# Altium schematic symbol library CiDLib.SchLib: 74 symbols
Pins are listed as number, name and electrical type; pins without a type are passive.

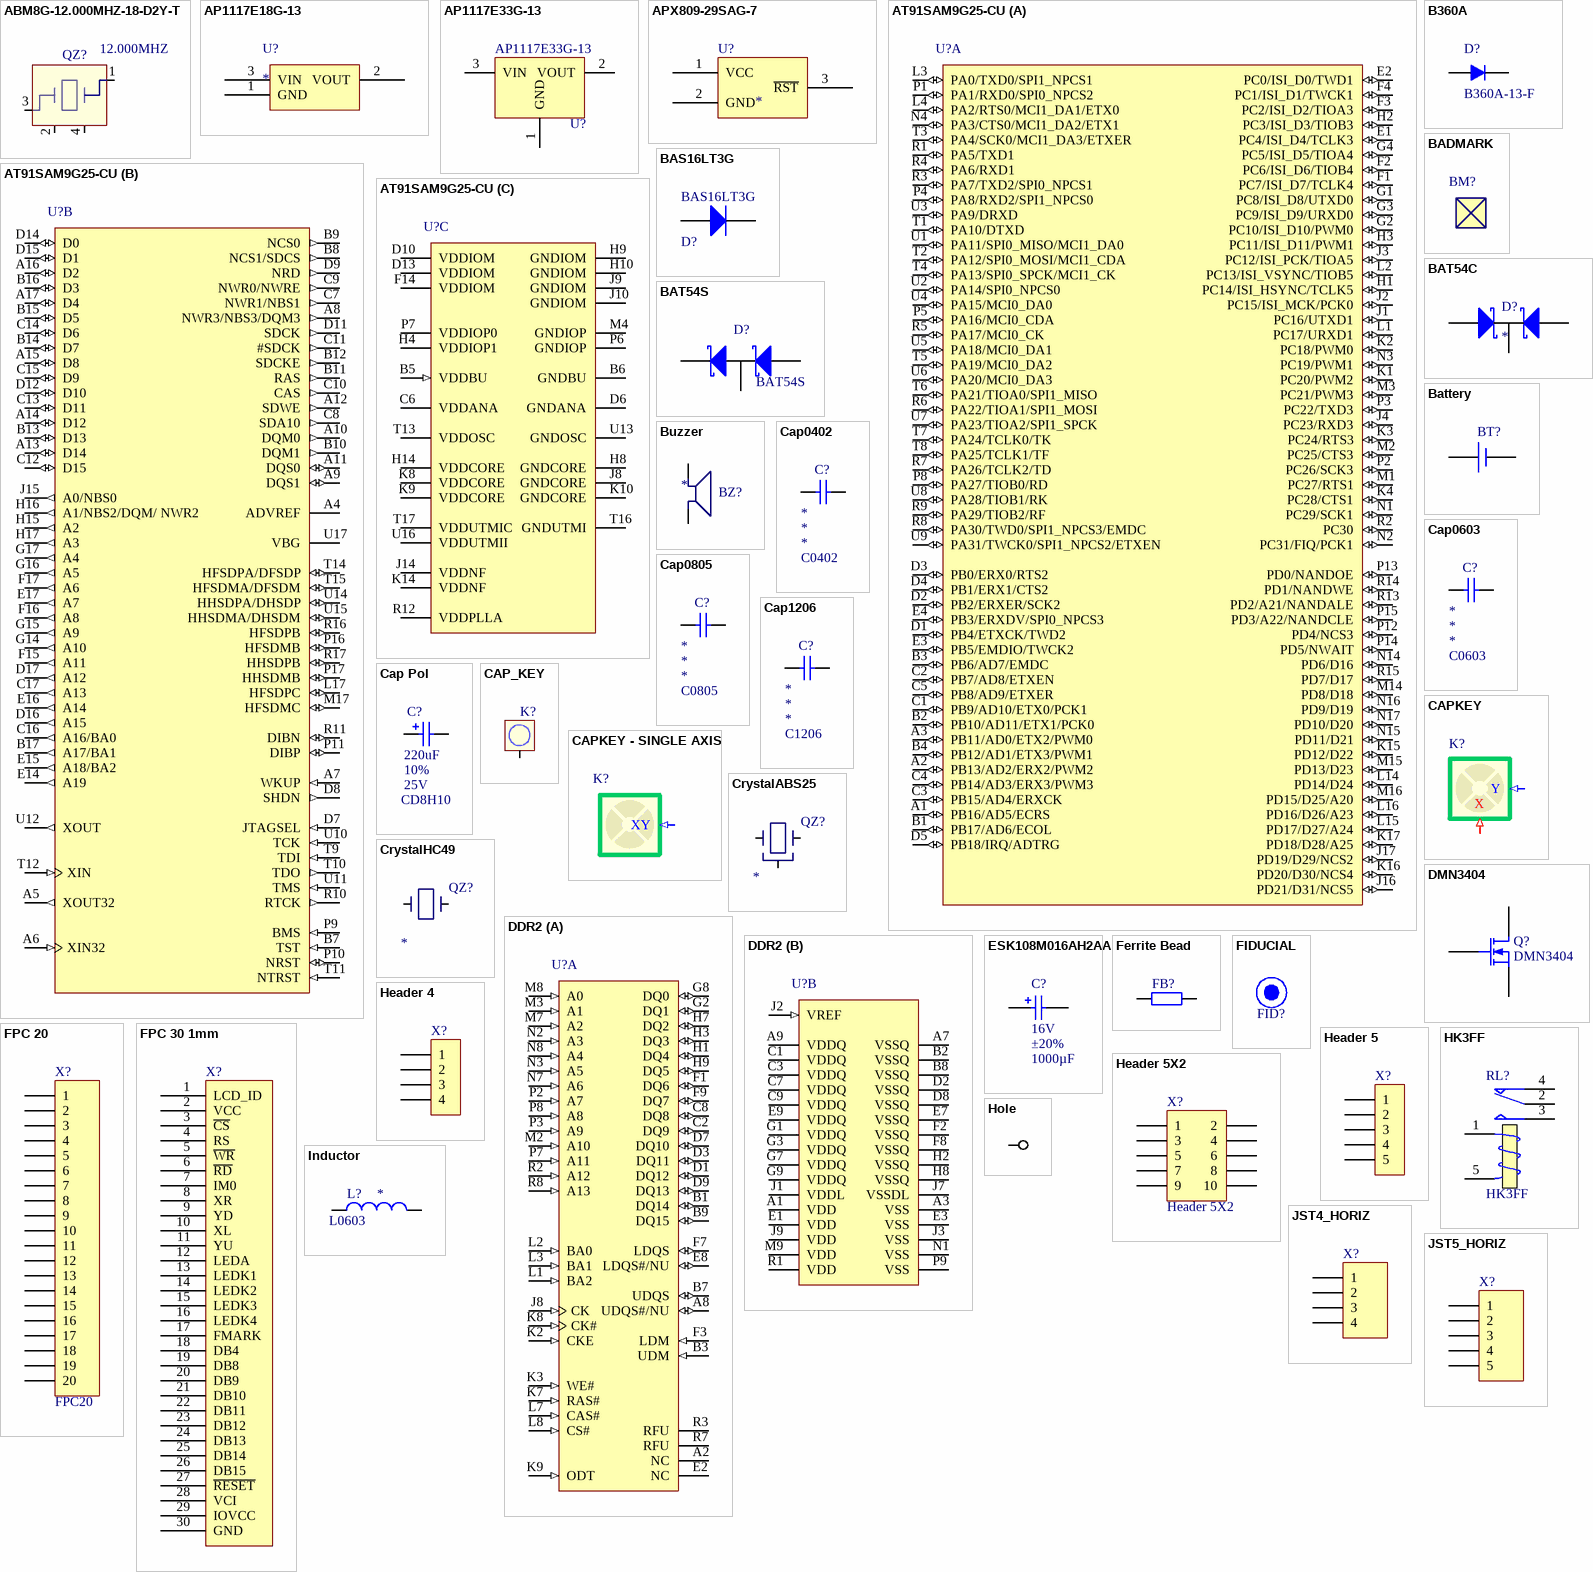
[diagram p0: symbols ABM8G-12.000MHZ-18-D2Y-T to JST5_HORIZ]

## ABM8G-12.000MHZ-18-D2Y-T
designator QZ?  value 12.000MHZ  (hidden comment: *)
footprint ABM8G-12.000MHZ-18-D2Y-T
pins: 1, 2, 3 1, 4

## AP1117E18G-13
designator U?
footprint SOT223 (SOT223, 4-Leads, Body 6,50x7,00mm (avg), Pitch 2,30mm, IPC Medium Density)
pins: 1 GND (power), 2 VOUT (power), 3 VIN (power)

## AP1117E33G-13
designator U?
footprint SOT223 (SOT223, 4-Leads, Body 6,50x7,00mm (avg), Pitch 2,30mm, IPC Medium Density)
pins: 1 GND (power), 2 VOUT (power), 3 VIN (power)

## APX809-29SAG-7
designator U?
Reset supervisor 2.9V
footprint SOT23-3
pins: 1 VCC (power), 2 GND (power), 3 ~{RST}

## AT91SAM9G25-CU
designator U?
AT91 ARM Thumb 32-bit Embedded MPU, 400MHz, 1V, Ethernet, HS USB, LPDDR/DDR2/MLC NAND support, 217-Pin BGA, Industrial Grade (-40°C to 85°C), Pb-Free; GROUP: G25
footprint BGA217
part A pins: A1 PB16/AD5/ECRS (io), A2 PB13/AD2/ERX2/PWM2 (io), A3 PB11/AD0/ETX2/PWM0 (io), B1 PB17/AD6/ECOL (io), B2 PB10/AD11/ETX1/PCK0 (io), B3 PB6/AD7/EMDC (io), B4 PB12/AD1/ETX3/PWM1 (io), C1 PB9/AD10/ETX0/PCK1 (io), C2 PB7/AD8/ETXEN (io), C3 PB15/AD4/ERXCK (io), C4 PB14/AD3/ERX3/PWM3 (io), C5 PB8/AD9/ETXER (io), D1 PB4/ETXCK/TWD2 (io), D2 PB2/ERXER/SCK2 (io), D3 PB0/ERX0/RTS2 (io), D4 PB1/ERX1/CTS2 (io), D5 PB18/IRQ/ADTRG (io), E1 PC4/ISI_D4/TCLK3 (io), E2 PC0/ISI_D0/TWD1 (io), E3 PB5/EMDIO/TWCK2 (io), E4 PB3/ERXDV/SPI0_NPCS3 (io), F1 PC7/ISI_D7/TCLK4 (io), F2 PC6/ISI_D6/TIOB4 (io), F3 PC2/ISI_D2/TIOA3 (io), F4 PC1/ISI_D1/TWCK1 (io), G1 PC8/ISI_D8/UTXD0 (io), G2 PC10/ISI_D10/PWM0 (io), G3 PC9/ISI_D9/URXD0 (io), G4 PC5/ISI_D5/TIOA4 (io), H1 PC14/ISI_HSYNC/TCLK5 (io), H2 PC3/ISI_D3/TIOB3 (io), H3 PC11/ISI_D11/PWM1 (io), J1 PC16/UTXD1 (io), J2 PC15/ISI_MCK/PCK0 (io), J3 PC12/ISI_PCK/TIOA5 (io), J4 PC23/RXD3 (io), J16 PD21/D31/NCS5 (io), J17 PD19/D29/NCS2 (io), K1 PC20/PWM2 (io), K2 PC18/PWM0 (io), K3 PC24/RTS3 (io), K4 PC28/CTS1 (io), K15 PD12/D22 (io), K16 PD20/D30/NCS4 (io), K17 PD18/D28/A25 (io), L1 PC17/URXD1 (io), L2 PC13/ISI_VSYNC/TIOB5 (io), L3 PA0/TXD0/SPI1_NPCS1 (io), L4 PA2/RTS0/MCI1_DA1/ETX0 (io), L14 PD14/D24 (io), L15 PD17/D27/A24 (io), L16 PD16/D26/A23 (io), M1 PC27/RTS1 (io), M2 PC25/CTS3 (io), M3 PC21/PWM3 (io), M14 PD8/D18 (io), M15 PD13/D23 (io), M16 PD15/D25/A20 (io), N1 PC29/SCK1 (io), N2 PC31/FIQ/PCK1 (io), N3 PC19/PWM1 (io), N4 PA3/CTS0/MCI1_DA2/ETX1 (io), N14 PD6/D16 (io), N15 PD11/D21 (io), N16 PD9/D19 (io), N17 PD10/D20 (io), P1 PA1/RXD0/SPI0_NPCS2 (io), P2 PC26/SCK3 (io), P3 PC22/TXD3 (io), P4 PA8/RXD2/SPI1_NPCS0 (io), P5 PA16/MCI0_CDA (io), P8 PA27/TIOB0/RD (io), P12 PD4/NCS3 (io), P13 PD0/NANDOE (io), P14 PD5/NWAIT (io), P15 PD3/A22/NANDCLE (io), R1 PA5/TXD1 (io), R2 PC30 (io), R3 PA7/TXD2/SPI0_NPCS1 (io), R4 PA6/RXD1 (io), R5 PA17/MCI0_CK (io), R6 PA22/TIOA1/SPI1_MOSI (io), R7 PA26/TCLK2/TD (io), R8 PA30/TWD0/SPI1_NPCS3/EMDC (io), R9 PA29/TIOB2/RF (io), R13 PD2/A21/NANDALE (io), R14 PD1/NANDWE (io), R15 PD7/D17 (io), T1 PA10/DTXD (io), T2 PA12/SPI0_MOSI/MCI1_CDA (io), T3 PA4/SCK0/MCI1_DA3/ETXER (io), T4 PA13/SPI0_SPCK/MCI1_CK (io), T5 PA19/MCI0_DA2 (io), T6 PA21/TIOA0/SPI1_MISO (io), T7 PA24/TCLK0/TK (io), T8 PA25/TCLK1/TF (io), U1 PA11/SPI0_MISO/MCI1_DA0 (io), U2 PA14/SPI0_NPCS0 (io), U3 PA9/DRXD (io), U4 PA15/MCI0_DA0 (io), U5 PA18/MCI0_DA1 (io), U6 PA20/MCI0_DA3 (io), U7 PA23/TIOA2/SPI1_SPCK (io), U8 PA28/TIOB1/RK (io), U9 PA31/TWCK0/SPI1_NPCS2/ETXEN (io)
part B pins: A4 ADVREF (power), A5 XOUT32 (out), A6 XIN32 (in), A7 WKUP (in), A8 NWR3/NBS3/DQM3 (out), A9 DQS1 (io), A10 DQM0 (out), A11 DQS0 (io), A12 SDWE (out), A13 D14 (io), A14 D12 (io), A15 D8 (io), A16 D2 (io), A17 D4 (io), B7 TST (in), B8 NCS1/SDCS (out), B9 NCS0 (out), B10 DQM1 (out), B11 RAS (out), B12 SDCKE (out), B13 D13 (io), B14 D7 (io), B15 D5 (io), B16 D3 (io), B17 A17/BA1 (out), C7 NWR1/NBS1 (out), C8 SDA10 (out), C9 NWR0/NWRE (out), C10 CAS (out), C11 #SDCK (out), C12 D15 (io), C13 D11 (io), C14 D6 (io), C15 D9 (io), C16 A16/BA0 (out), C17 A13 (out), D7 JTAGSEL (in), D8 SHDN (out), D9 NRD (out), D11 SDCK (out), D12 D10 (io), D14 D0 (io), D15 D1 (io), D16 A15 (out), D17 A12 (out), E14 A19 (out), E15 A18/BA2 (out), E16 A14 (out), E17 A7 (out), F15 A11 (out), F16 A8 (out), F17 A6 (out), G14 A10 (out), G15 A9 (out), G16 A5 (out), G17 A4 (out), H15 A2 (out), H16 A1/NBS2/DQM/ NWR2 (out), H17 A3 (out), J15 A0/NBS0 (out), L17 HFSDPC (io), M17 HFSDMC (io), P9 BMS (in), P10 NRST (io), P11 DIBP (io), P16 HFSDMB (io), P17 HHSDMB (io), R10 RTCK (out), R11 DIBN (io), R16 HFSDPB (io), R17 HHSDPB (io), T9 TDI (in), T10 TDO (out), T11 NTRST (in), T12 XIN (in), T14 HFSDPA/DFSDP (io), T15 HFSDMA/DFSDM (io), U10 TCK (in), U11 TMS (in), U12 XOUT (out), U14 HHSDPA/DHSDP (io), U15 HHSDMA/DHSDM (io), U17 VBG (power)
part C pins: B5 VDDBU (in), B6 GNDBU (power), C6 VDDANA (power), D6 GNDANA (power), D10 VDDIOM (power), D13 VDDIOM (power), F14 VDDIOM (power), H4 VDDIOP1 (power), H8 GNDCORE (power), H9 GNDIOM (power), H10 GNDIOM (power), H14 VDDCORE (power), J8 GNDCORE (power), J9 GNDIOM (power), J10 GNDIOM (power), J14 VDDNF (power), K8 VDDCORE (power), K9 VDDCORE (power), K10 GNDCORE (power), K14 VDDNF (power), M4 GNDIOP (power), P6 GNDIOP (power), P7 VDDIOP0 (power), R12 VDDPLLA (power), T13 VDDOSC (power), T16 GNDUTMI (power), T17 VDDUTMIC (power), U13 GNDOSC (power), U16 VDDUTMII (power)

## B360A
designator D?, comment B360A-13-F
B360A Diode; Manufacturer: Diodes Incorporated; Diode Type: Schottky; Voltage - DC Reverse (Vr) (Max): 60V; Current - Average Rectified (Io): 3A; Voltage - Forward (Vf) (Max) @ If: 700mV @ 3A; Speed: Fast Recovery =< 500ns, > 200mA (Io); Current - Reverse Leakage @ Vr: 500µA @ 60V; Capacitance @ Vr, F: 200pF @ 4V, 1MHz
footprint SMA
pins: 1 A, 2 K

## BADMARK
designator BM?  (value not drawn)
Bad Mark Indicator
footprint BADMARK

## BAS16LT3G
designator D?  Manufacturer Part Number: BAS16LT3G  (hidden comment: *)
DIODE GEN PURP 75V 200MA SOT23-3; Manufacturer: ON Semiconductor; Diode Type: Standard; Current - Average Rectified (Io): 200mA (DC); Voltage - Forward (Vf) (Max) @ If: 1.25V @ 150mA; Speed: Small Signal =< 200mA (Io), Any Speed; Reverse Recovery Time (trr): 6ns; Current - Reverse Leakage @ Vr: 1µA @ 75V; Capacitance @ Vr, F: 2pF @ 0V, 1MHz
footprint BAS16LT3G
pins: 1 A, 3 K

## BAT54C
designator D?
Common cathode dual Schottky diode
footprint SOT23-3
pins: 1 K, 2 A1, 3 A2

## BAT54S
designator D?
DIODE ARRAY SCHOTTKY 30V SOT23
footprint SOT23-3
pins: 1 K, 2 A2, 3 A1

## Battery
designator BT?
Multicell Battery
footprint CR2032-SMD (CR2032 Battery holder (SMD))
pins: 1 + (power), 2 - (power)

## Buzzer
designator BZ?
Standard PTH Buzzer
footprint Buzzer
pins: 1, 2

## Cap0402
designator C?  (value not drawn)
Capacitor
simulation model CAP (Capacitor)
signal-integrity model Cap
footprint C0402 (Chip Capacitor, 2-Leads, Body 1,00x0,50mm, IPC Medium Density)
pins: 1, 2

## Cap0603
designator C?  (value not drawn)
Capacitor
simulation model CAP (Capacitor)
signal-integrity model Cap
footprint C0603 (Chip Capacitor, 2-Leads, Body 1,60x0,80mm, IPC Medium Density)
pins: 1, 2

## Cap0805
designator C?  (value not drawn)
Capacitor
simulation model CAP (Capacitor)
signal-integrity model Cap
footprint C0805 (Chip Capacitor, 2-Leads, Body 2,00x1,25mm, IPC Medium Density)
pins: 1, 2

## Cap1206
designator C?  (value not drawn)
Capacitor
simulation model CAP (Capacitor)
signal-integrity model Cap
footprint C1206 (Chip Capacitor, 2-Leads, Body 3,20x1,60mm, IPC Medium Density)
pins: 1, 2

## Cap Pol
designator C?  value 220uF  Tolerance: 10%  MAX VDC: 25V  (hidden comment: Cap Pol)
Polarized Capacitor
simulation model CAP (Capacitor)
signal-integrity model Cap Pol ([Unknown model type, plugin missing])
footprint CD8H10 (Aluminum Electrolytic Capacitor, Body 8,30x8,30x10,50mm, IPC Medium Density)
pins: 1, 2
1 alternate drawing of the same symbol

## CAP_KEY
designator K?  (value not drawn)
footprint CAPKEY - NEW
pins: 1

## CAPKEY
designator K?  (value not drawn)
Capacitive touch key
footprint CAPKEY
pins: X (in), Y (in)

## CAPKEY - SINGLE AXIS
designator K?  (value not drawn)
Capacitive touch key
footprint CAPKEY - SINGLE AXIS
pins: XY (in)

## CrystalABS25
designator QZ?
ABS25-32.768KHZ-T
footprint ABS25 (Crystal 32.768kHz)
pins: 1 X1, 4 X2, G X1

## CrystalHC49
designator QZ?
footprint HC49
pins: 1 X1, 2 X2

## DDR2
designator U?
DDR2 Memory; GROUP: MT47H
footprint BGA84
part A pins: A2 NC "No connect: These balls should be left unconnected.", A8 UDQS#/NU (io) "Data strobe for upper byte: Output with read data, input with write data for source synchronous operation. Edge-aligned with read data, center-aligned with write data. UDQS# is only used when differential data strobe mode is (See Datasheet)", B1 DQ14 (io) "Data input/output: Bidirectional data bus for 128 Meg x 16.", B3 UDM (in) "Input data mask: DM is an input mask signal for write data. Input data is masked when DM is concurrently sampled HIGH during a WRITE access. DM is sampled on both edges of DQS. Although DM balls are input-only, the DM (See Datasheet)", B7 UDQS (io) "Data strobe for upper byte: Output with read data, input with write data for source synchronous operation. Edge-aligned with read data, center-aligned with write data. UDQS# is only used when differential data strobe mode is (See Datasheet)", B9 DQ15 (io) "Data input/output: Bidirectional data bus for 128 Meg x 16.", C2 DQ9 (io) "Data input/output: Bidirectional data bus for 128 Meg x 16.", C8 DQ8 (io) "Data input/output: Bidirectional data bus for 128 Meg x 16.", D1 DQ12 (io) "Data input/output: Bidirectional data bus for 128 Meg x 16.", D3 DQ11 (io) "Data input/output: Bidirectional data bus for 128 Meg x 16.", D7 DQ10 (io) "Data input/output: Bidirectional data bus for 128 Meg x 16.", D9 DQ13 (io) "Data input/output: Bidirectional data bus for 128 Meg x 16.", E2 NC "No connect: These balls should be left unconnected.", E8 LDQS#/NU (io) "Data strobe for lower byte: Output with read data, input with write data for source synchronous operation. Edge-aligned with read data, center-aligned with write data. LDQS# is only used when differential data strobe mode is (See Datasheet)", F1 DQ6 (io) "Data input/output: Bidirectional data bus for 128 Meg x 16.", F3 LDM (in) "Input data mask: DM is an input mask signal for write data. Input data is masked when DM is concurrently sampled HIGH during a WRITE access. DM is sampled on both edges of DQS. Although DM balls are input-only, the DM (See Datasheet)", F7 LDQS (io) "Data strobe for lower byte: Output with read data, input with write data for source synchronous operation. Edge-aligned with read data, center-aligned with write data. LDQS# is only used when differential data strobe mode is (See Datasheet)", F9 DQ7 (io) "Data input/output: Bidirectional data bus for 128 Meg x 16.", G2 DQ1 (io) "Data input/output: Bidirectional data bus for 128 Meg x 16.", G8 DQ0 (io) "Data input/output: Bidirectional data bus for 128 Meg x 16.", H1 DQ4 (io) "Data input/output: Bidirectional data bus for 128 Meg x 16.", H3 DQ3 (io) "Data input/output: Bidirectional data bus for 128 Meg x 16.", H7 DQ2 (io) "Data input/output: Bidirectional data bus for 128 Meg x 16.", H9 DQ5 (io) "Data input/output: Bidirectional data bus for 128 Meg x 16.", J8 CK (in) "Clock: CK and CK# are differential clock inputs. All address and control input signals are sampled on the crossing of the positive edge of CK and negative edge of CK#. Output data (DQ and DQS/DQS#) is referenced to the (See Datasheet)", K2 CKE (in) "Clock enable: CKE (registered HIGH) activates and CKE (registered LOW) deactivates clocking circuitry on the DDR2 SDRAM. The specific circuitry that is enabled/disabled is dependent on the DDR2 SDRAM configuration and (See Datasheet)", K3 WE# (in) "Command inputs: RAS#, CAS#, and WE# (along with CS#) define the command being entered.", K7 RAS# (in) "Command inputs: RAS#, CAS#, and WE# (along with CS#) define the command being entered.", K8 CK# (in) "Clock: CK and CK# are differential clock inputs. All address and control input signals are sampled on the crossing of the positive edge of CK and negative edge of CK#. Output data (DQ and DQS/DQS#) is referenced to the (See Datasheet)", K9 ODT (in) "On-die termination: ODT (registered HIGH) enables termination resistance internal to the DDR2 SDRAM. When enabled, ODT is only applied to each of the following balls: DQ[15:0], LDM, UDM, LDQS, LDQS#, UDQS, and UDQS# for the (See Datasheet)", L1 BA2 (in) "Bank address inputs: BA[2:0] define to which bank an ACTIVE, READ, WRITE, or PRECHARGE command is being applied. BA[2:0] define which mode register, including MR, EMR, EMR(2), and EMR(3), is loaded during the LOAD MODE (See Datasheet)", L2 BA0 (in) "Bank address inputs: BA[2:0] define to which bank an ACTIVE, READ, WRITE, or PRECHARGE command is being applied. BA[2:0] define which mode register, including MR, EMR, EMR(2), and EMR(3), is loaded during the LOAD MODE (See Datasheet)", L3 BA1 (in) "Bank address inputs: BA[2:0] define to which bank an ACTIVE, READ, WRITE, or PRECHARGE command is being applied. BA[2:0] define which mode register, including MR, EMR, EMR(2), and EMR(3), is loaded during the LOAD MODE (See Datasheet)", L7 CAS# (in) "Command inputs: RAS#, CAS#, and WE# (along with CS#) define the command being entered.", L8 CS# (in) "Chip select: CS# enables (registered LOW) and disables (registered HIGH) the command decoder. All commands are masked when CS# is registered high. CS# provides for external bank selection on systems with multiple ranks. CS# (See Datasheet)", M2 A10 (in) "Address inputs: Provide the row address for ACTIVE commands, and the column address and auto precharge bit (A10) for READ/WRITE commands, to select one location out of the memory array in the respective bank. A10 sampled (See Datasheet)", M3 A1 (in) "Address inputs: Provide the row address for ACTIVE commands, and the column address and auto precharge bit (A10) for READ/WRITE commands, to select one location out of the memory array in the respective bank. A10 sampled (See Datasheet)", M7 A2 (in) "Address inputs: Provide the row address for ACTIVE commands, and the column address and auto precharge bit (A10) for READ/WRITE commands, to select one location out of the memory array in the respective bank. A10 sampled (See Datasheet)", M8 A0 (in) "Address inputs: Provide the row address for ACTIVE commands, and the column address and auto precharge bit (A10) for READ/WRITE commands, to select one location out of the memory array in the respective bank. A10 sampled (See Datasheet)", N2 A3 (in) "Address inputs: Provide the row address for ACTIVE commands, and the column address and auto precharge bit (A10) for READ/WRITE commands, to select one location out of the memory array in the respective bank. A10 sampled (See Datasheet)", N3 A5 (in) "Address inputs: Provide the row address for ACTIVE commands, and the column address and auto precharge bit (A10) for READ/WRITE commands, to select one location out of the memory array in the respective bank. A10 sampled (See Datasheet)", N7 A6 (in) "Address inputs: Provide the row address for ACTIVE commands, and the column address and auto precharge bit (A10) for READ/WRITE commands, to select one location out of the memory array in the respective bank. A10 sampled (See Datasheet)", N8 A4 (in) "Address inputs: Provide the row address for ACTIVE commands, and the column address and auto precharge bit (A10) for READ/WRITE commands, to select one location out of the memory array in the respective bank. A10 sampled (See Datasheet)", P2 A7 (in) "Address inputs: Provide the row address for ACTIVE commands, and the column address and auto precharge bit (A10) for READ/WRITE commands, to select one location out of the memory array in the respective bank. A10 sampled (See Datasheet)", P3 A9 (in) "Address inputs: Provide the row address for ACTIVE commands, and the column address and auto precharge bit (A10) for READ/WRITE commands, to select one location out of the memory array in the respective bank. A10 sampled (See Datasheet)", P7 A11 (in) "Address inputs: Provide the row address for ACTIVE commands, and the column address and auto precharge bit (A10) for READ/WRITE commands, to select one location out of the memory array in the respective bank. A10 sampled (See Datasheet)", P8 A8 (in) "Address inputs: Provide the row address for ACTIVE commands, and the column address and auto precharge bit (A10) for READ/WRITE commands, to select one location out of the memory array in the respective bank. A10 sampled (See Datasheet)", R2 A12 (in) "Address inputs: Provide the row address for ACTIVE commands, and the column address and auto precharge bit (A10) for READ/WRITE commands, to select one location out of the memory array in the respective bank. A10 sampled (See Datasheet)", R3 RFU "Reserved for future use: Row address bits A14 (R3), A15 (R7) on the x16, and A15 (L7) on the x4/x8.", R7 RFU "Reserved for future use: Row address bits A14 (R3), A15 (R7) on the x16, and A15 (L7) on the x4/x8.", R8 A13 (in) "Address inputs: Provide the row address for ACTIVE commands, and the column address and auto precharge bit (A10) for READ/WRITE commands, to select one location out of the memory array in the respective bank. A10 sampled (See Datasheet)"
part B pins: A1 VDD (power) "Power supply: 1.8V +/-0.1V.", A3 VSS (power) "Ground.", A7 VSSQ (power) "DQ ground: Isolated on the device for improved noise immunity.", A9 VDDQ (power) "DQ power supply: 1.8V +/-0.1V. Isolated on the device for improved noise immunity.", B2 VSSQ (power) "DQ ground: Isolated on the device for improved noise immunity.", B8 VSSQ (power) "DQ ground: Isolated on the device for improved noise immunity.", C1 VDDQ (power) "DQ power supply: 1.8V +/-0.1V. Isolated on the device for improved noise immunity.", C3 VDDQ (power) "DQ power supply: 1.8V +/-0.1V. Isolated on the device for improved noise immunity.", C7 VDDQ (power) "DQ power supply: 1.8V +/-0.1V. Isolated on the device for improved noise immunity.", C9 VDDQ (power) "DQ power supply: 1.8V +/-0.1V. Isolated on the device for improved noise immunity.", D2 VSSQ (power) "DQ ground: Isolated on the device for improved noise immunity.", D8 VSSQ (power) "DQ ground: Isolated on the device for improved noise immunity.", E1 VDD (power) "Power supply: 1.8V +/-0.1V.", E3 VSS (power) "Ground.", E7 VSSQ (power) "DQ ground: Isolated on the device for improved noise immunity.", E9 VDDQ (power) "DQ power supply: 1.8V +/-0.1V. Isolated on the device for improved noise immunity.", F2 VSSQ (power) "DQ ground: Isolated on the device for improved noise immunity.", F8 VSSQ (power) "DQ ground: Isolated on the device for improved noise immunity.", G1 VDDQ (power) "DQ power supply: 1.8V +/-0.1V. Isolated on the device for improved noise immunity.", G3 VDDQ (power) "DQ power supply: 1.8V +/-0.1V. Isolated on the device for improved noise immunity.", G7 VDDQ (power) "DQ power supply: 1.8V +/-0.1V. Isolated on the device for improved noise immunity.", G9 VDDQ (power) "DQ power supply: 1.8V +/-0.1V. Isolated on the device for improved noise immunity.", H2 VSSQ (power) "DQ ground: Isolated on the device for improved noise immunity.", H8 VSSQ (power) "DQ ground: Isolated on the device for improved noise immunity.", J1 VDDL (power) "DLL power supply: 1.8V +/-0.1V.", J2 VREF (in) "SSTL_18 reference voltage.", J3 VSS (power) "Ground.", J7 VSSDL (power) "DLL ground: Isolated on the device from VSS and VSSQ.", J9 VDD (power) "Power supply: 1.8V +/-0.1V.", M9 VDD (power) "Power supply: 1.8V +/-0.1V.", N1 VSS (power) "Ground.", P9 VSS (power) "Ground.", R1 VDD (power) "Power supply: 1.8V +/-0.1V."

## DMN3404
designator Q?
DMN3404 N-Channel MOSFET
footprint SOT23-3
pins: 1 D, 2 G, 3 S

## ESK108M016AH2AA
designator C?  Capacitance: 1000µF  Tolerance: ±20%  Voltage Rating: 16V  (hidden comment: *)
CAP ALUM 1000UF 20% 16V RADIAL; Manufacturer: Kemet; Manufacturer Part Number: ESK108M016AH2AA; Lifetime @ Temp.: 2000 Hrs @ 85°C; Polarization: Polar; Ripple Current: 630mA @ 120Hz
footprint ESK108M016AH2AA (CAP ALUM 1000UF 20% 16V RADIAL)
pins: 1, 2

## Ferrite Bead
designator FB?  (value not drawn)
footprint FB0402
pins: 1, 2

## FIDUCIAL
designator FID?  (value not drawn)  (no BOM)
Standard fiducial for Control iD boards; PCB Info: DNP
footprint FIDUCIAL-1p5X3

## FPC 20
designator X?, comment FPC20
FPC, 20-Pin
footprint 0.5A-20PB
pins: 1, 2, 3, 4, 5, 6, 7, 8, 9, 10, 11, 12, 13, 14, 15, 16, 17, 18, 19, 20

## FPC 30 1mm
designator X?  (value not drawn)
Horizontal FPC 30 positions 1mm pitch
footprint FPC_Horizontal_30_1mm (Horizontal FPC connector with 30 leads and 1mm pitch)
footprint FPC_Horizontal_30_1mm-INVERTED (Horizontal FPC connector with 30 leads and 1mm pitch)
pins: 1 LCD_ID, 2 VCC, 3 ~{CS}, 4 RS, 5 ~{WR}, 6 ~{RD}, 7 IM0, 8 XR, 9 YD, 10 XL, 11 YU, 12 LEDA, 13 LEDK1, 14 LEDK2, 15 LEDK3, 16 LEDK4, 17 FMARK, 18 DB4, 19 DB8, 20 DB9, 21 DB10, 22 DB11, 23 DB12, 24 DB13, 25 DB14, 26 DB15, 27 ~{RESET}, 28 VCI, 29 IOVCC, 30 GND

## Header 4
designator X?  (value not drawn)
Header, 4-Pin, Single row, 0.1"
footprint 1X04
pins: 1, 2, 3, 4

## Header 5
designator X?  (value not drawn)
Header, 5-Pin, Single row, 0.1"
footprint 1X05
pins: 1, 2, 3, 4, 5

## Header 5X2
designator X?
Header, 5-Pin, Dual row
footprint HEADER2x5 1.27
pins: 1, 2, 3, 4, 5, 6, 7, 8, 9, 10

## HK3FF
designator RL?
SPDT Relay HK3FF
footprint HK3FF
pins: 1 T1, 2 COM, 3 NO, 4 NC, 5 T2

## Hole
designator HOLE?  (value not drawn)
footprint Hole (PTH Hole for wire soldering)
pins: 1

## Inductor
designator L?  (value not drawn)
simulation model INDUCTOR (Inductor)
signal-integrity model Inductor
footprint L0603
pins: 1, 2

## JST4_HORIZ
designator X?  (value not drawn)
Header, 4-Pin
footprint JST4_HORIZ (SMT Horizontal JST 4 leads connector)
pins: 1, 2, 3, 4

## JST5_HORIZ
designator X?  (value not drawn)
Header, 5-Pin
footprint JST5_HORIZ (SMT Horizontal JST 5 leads connector)
pins: 1, 2, 3, 4, 5

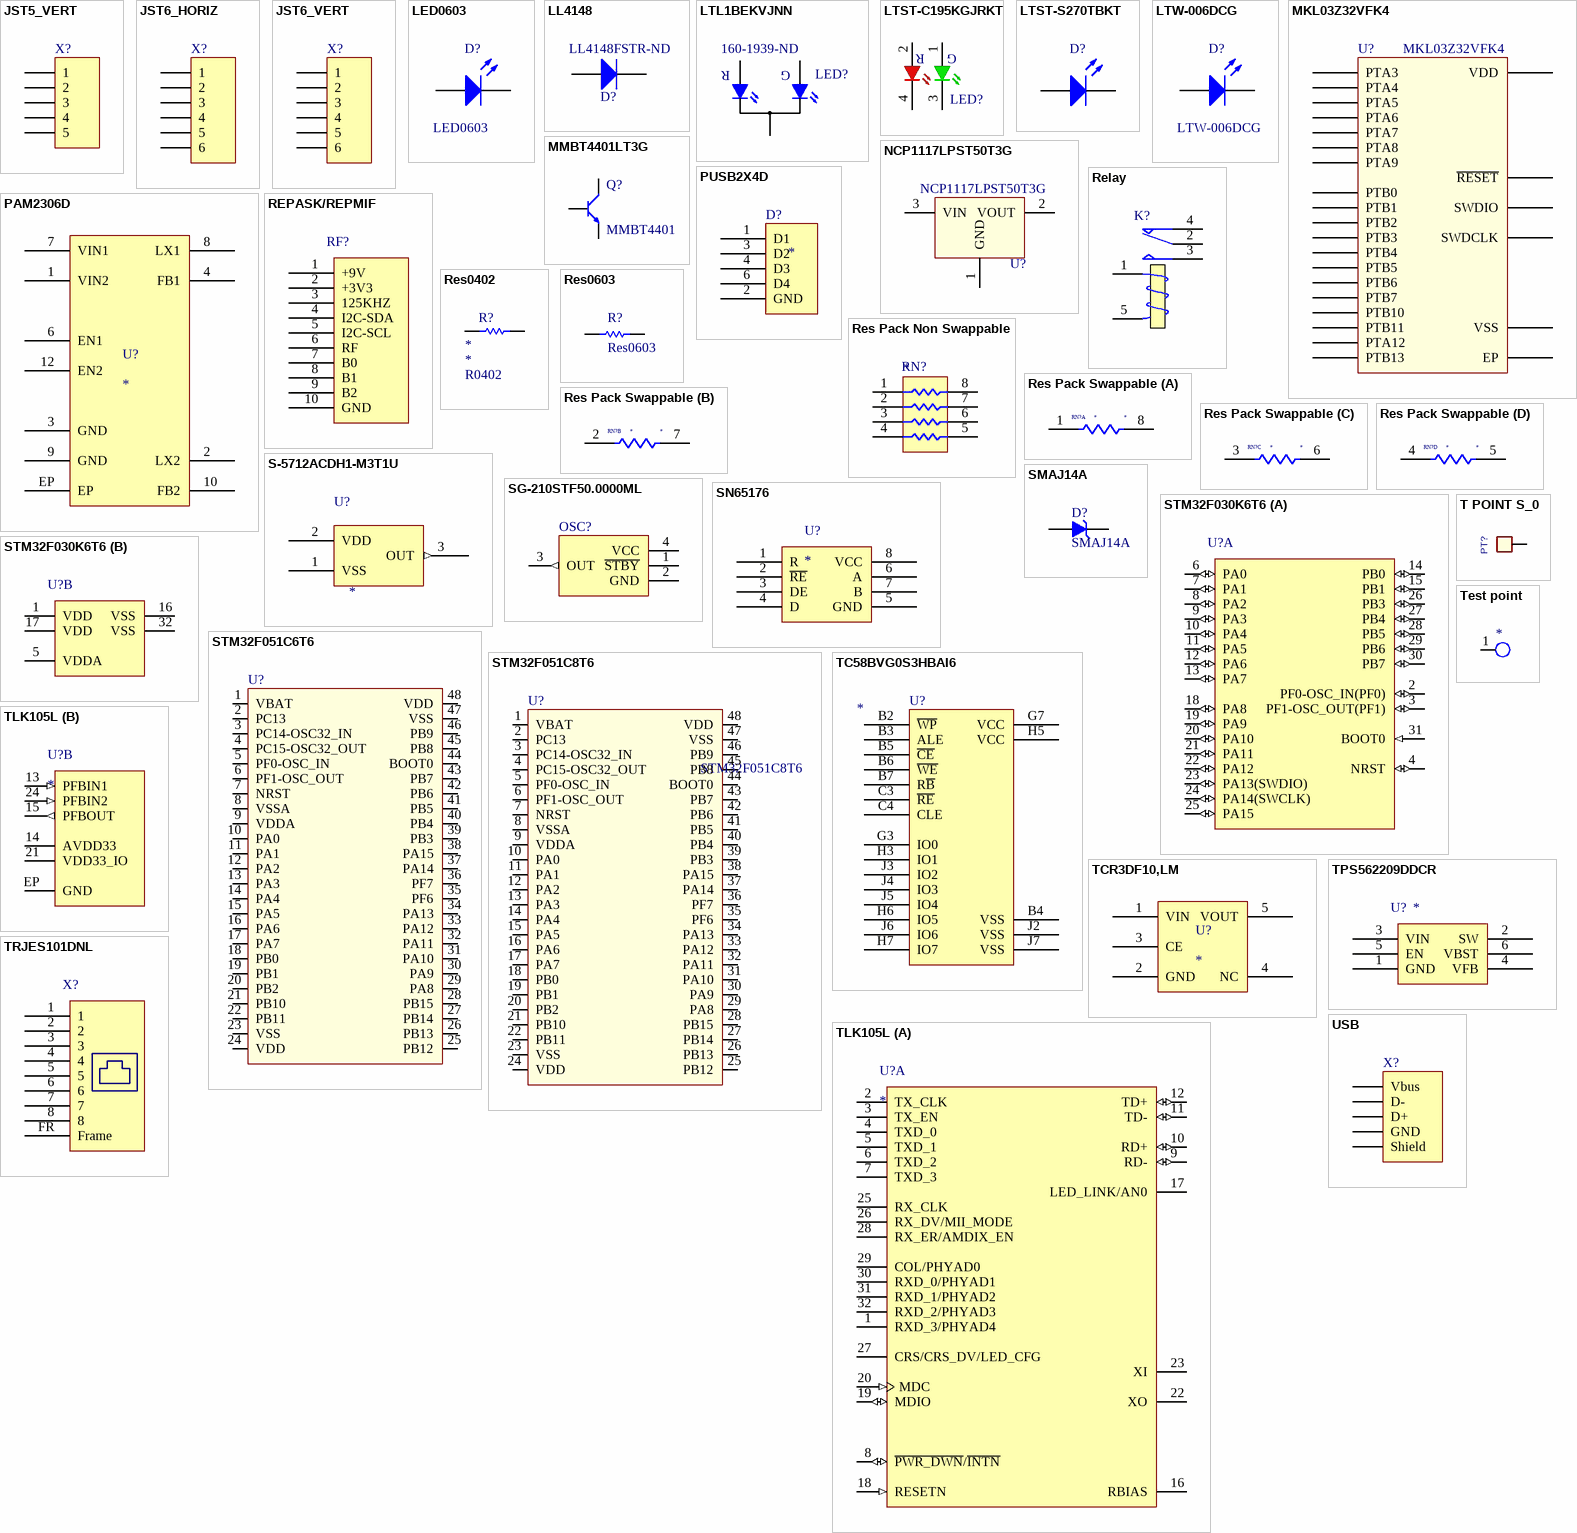
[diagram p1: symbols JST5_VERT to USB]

## JST5_VERT
designator X?  (value not drawn)
Header, 5-Pin
footprint JST5_VERT
pins: 1, 2, 3, 4, 5

## JST6_HORIZ
designator X?  (value not drawn)
Header, 6-Pin
footprint JST6_HORIZ (SMT Horizontal JST 6 leads connector)
pins: 1, 2, 3, 4, 5, 6

## JST6_VERT
designator X?  (value not drawn)
Header, 6-Pin
footprint JST6_VERT
pins: 1, 2, 3, 4, 5, 6

## LED0603
designator D?  (value not drawn)
Light-Emitting Diode
footprint LED0603
pins: 1 A, 2 K

## LL4148
designator D?  Supplier Part Number 1: LL4148FSTR-ND  (hidden comment: LL4148)
DIODE GEN PURP 100V 200MA LL34
footprint SOD-80
pins: 1 A, 2 K

## LTL1BEKVJNN
designator LED?  Supplier Part Number 1: 160-1939-ND  (hidden comment: LTL1BEKVJNN)
LED GRN/RED DIFF 3MM ROUND T/H; Manufacturer: Lite-On Inc.; Color: Green, Red; Lens Color: White; Lens Transparency: Diffused; Millicandela Rating: 110mcd Green, 110mcd Red; Lens Style/Size: Round with Domed Top, 3.00mm; Voltage - Forward (Vf) (Typ): 2.1V Green, 2V Red; Current - Test: 20mA Green, 20mA Red; Viewing Angle: 45°; Wavelength - Dominant: 572nm Green, 631nm Red; Wavelength - Peak: 575nm Green, 639nm Red
footprint LTL1BEKVJNN (LED GRN/RED DIFF 3MM ROUND T/H)
pins: 1 AR, 2 K, 3 AG

## LTST-C195KGJRKT
designator LED?  (value not drawn)
Green-Red 571nm Green 631nm 2V-2V 0606
footprint LTST-C195KGJRKT (Green-Red 571nm 631nm 2V-2V  0606)
pins: 1 AG, 2 AR, 3 KG, 4 KR

## LTST-S270TBKT
designator D?  (value not drawn)
Light-Emitting Diode (side-emitting)
footprint LTST-S270TBKT
pins: 1 A, 2 K

## LTW-006DCG
designator D?  (value not drawn)
Light-Emitting Diode (side-emitting)
footprint LTW-006DCG
pins: 1 A, 2 K

## MKL03Z32VFK4
designator U?
IC MCU 32BIT 32KB FLASH 24QFN
footprint QFN24
pins: 1 PTB6, 2 PTB7, 3 VDD, 4 VSS, 5 PTA3, 6 PTA4, 7 PTA5, 8 PTA6, 9 PTB10, 10 PTB11, 11 PTA7, 12 PTB0, 13 PTB1, 14 PTB2, 15 PTA8, 16 PTA9, 17 PTB3, 18 PTB4, 19 PTB5, 20 PTA12, 21 PTB13, 22 SWDCLK, 23 ~{RESET}, 24 SWDIO, 25 EP

## MMBT4401LT3G
designator Q?, comment MMBT4401
TRANS NPN 40V 0.6A SOT-23; Manufacturer: ON Semiconductor; Manufacturer Part Number: MMBT4401LT3G; Current - Collector (Ic) (Max): 600mA; Vce Saturation (Max) @ Ib, Ic: 750mV @ 50mA, 500mA; DC Current Gain (hFE) (Min) @ Ic, Vce: 100 @ 150mA, 1V; Power - Max: 300mW; Frequency - Transition: 250MHz
footprint SOT23-3
pins: 1, 2, 3

## NCP1117LPST50T3G
designator U?
IC REG LDO 5V 1A SOT223; Manufacturer: ON Semiconductor; Regulator Topology: Positive Fixed; Voltage - Dropout (Typical): 1.3V @ 1A; Number of Regulators: 1; Voltage - Input: Up to 18V; Current - Limit (Min): 1.1A
footprint SOT223 (SOT223, 4-Leads, Body 6,50x7,00mm (avg), Pitch 2,30mm, IPC Medium Density)
pins: 1 GND (power), 2 VOUT (power), 3 VIN (power)

## PAM2306D
designator U?
Dual switching Step-Down regulator
pins: 1 VIN2 (power), 2 LX2, 3 GND (power), 4 FB1, 6 EN1, 7 VIN1 (power), 8 LX1, 9 GND (power), 10 FB2, 12 EN2, EP (power)

## PUSB2X4D
designator D?
USB ESD protection diodes
footprint SOT457 (SC-74)
pins: 1 D1, 2 GND, 3 D2, 4 D3, 6 D4

## Relay
designator K?
SPDT Relay
footprint RELE
pins: 1 T1, 2 COM, 3 NO, 4 NC, 5 T2

## REPASK/REPMIF
designator RF?  (value not drawn)
Control iD RF Module
footprint REPASK_REPMIF
pins: 1 +9V, 2 +3V3, 3 125KHZ, 4 I2C-SDA, 5 I2C-SCL, 6 RF, 7 B0, 8 B1, 9 B2, 10 GND

## Res0402
designator R?  (value not drawn)
Resistor
simulation model RESISTOR (Resistor)
signal-integrity model Res
footprint R0402
pins: 1, 2

## Res0603
designator R?
Resistor
footprint R0603 (Chip Resistor, 2-Leads, Body 1.60x0.80mm, IPC Medium Density)
pins: 1, 2

## Res Pack Non Swappable
designator RN?
Isolated Resistor Network
footprint RN0804 (Chip Array, ConvexS, 8-Leads, Pitch 0,50mm,  Body 2,00x1,00mm,  IPC Medium Density)
pins: 1, 2, 3, 4, 5, 6, 7, 8

## Res Pack Swappable
designator RN?  (value not drawn)
Isolated Resistor Network - Parts
footprint RN0804 (Chip Array, ConvexS, 8-Leads, Pitch 0,50mm,  Body 2,00x1,00mm,  IPC Medium Density)
part A pins: 1, 8
part B pins: 2, 7
part C pins: 3, 6
part D pins: 4, 5

## S-5712ACDH1-M3T1U
designator U?
Hall effect sensor from Seiko
footprint SOT23-3
pins: 1 VSS (power), 2 VDD (power), 3 OUT (out)

## SG-210STF50.0000ML
designator OSC?  (value not drawn)
Seiko Epson 50MHz Oscillator
footprint XTAL-2.5X2MM-EPSON
pins: 1 ~{STBY}, 2 GND (power), 3 OUT (out), 4 VCC (power)

## SMAJ14A
designator D?
TVS DIODE 14VWM 23.2VC SMA; Manufacturer: Littelfuse Inc.; Type: Zener; Unidirectional Channels: 1; Voltage - Reverse Standoff (Typ): 14V; Voltage - Breakdown (Min): 15.6V; Voltage - Clamping (Max) @ Ipp: 23.2V; Current - Peak Pulse (10/1000µs): 17.2A; Power - Peak Pulse: 400W; Power Line Protection: No
footprint SMA
pins: 1 A, 2 K

## SN65176
designator U?
RS485 Transceiver
footprint SOIC8 (SOIC, 8-Leads, Body 6,20x5,30mm, Pitch 1,27mm, IPC Medium Density)
pins: 1 R, 2 ~{RE}, 3 DE, 4 D, 5 GND, 6 A, 7 B, 8 VCC

## STM32F030K6T6
designator U?
ARM Cortex-M0 32-bit MCU, 32 KB Flash, 4 KB Internal RAM, 26 I/Os, 32-pin LQFP, -40 to 85 degC, Tray; PartNumber: STM32F030K6T6; FLASH Size (Prog) (kB): 32; I/Os (High Current): 26; Internal RAM Size (kB): 4; Operating Frequency(F) (Processor speed) (MHz): 48; Supply Voltage(Vcc) min (V): 2.4
footprint STM-LQFP32_N (QFP, 32-Leads, Body 7x7mm, Pitch 0.8mm, IPC Medium Density)
footprint STM-LQFP32_L (QFP, 32-Leads, Body 7x7mm, Pitch 0.8mm, IPC High Density)
footprint STM-LQFP32_M (QFP, 32-Leads, Body 7x7mm, Pitch 0.8mm, IPC Low Density)
part A pins: 2 PF0-OSC_IN(PF0) (io) "PF0-OSC_IN(PF0)/OSC_IN", 3 PF1-OSC_OUT(PF1) (io) "PF1-OSC_OUT(PF1)/OSC_OUT", 4 NRST (io) "Device reset input / internal reset output (active low)", 6 PA0 (io) "PA0/USART1_CTS/ADC_IN0,RTC_TAMP2,WKUP1", 7 PA1 (io) "PA1/USART1_RTS,EVENTOUT/ADC_IN1", 8 PA2 (io) "PA2/USART1_TX/ADC_IN2", 9 PA3 (io) "PA3/USART1_RX/ADC_IN3", 10 PA4 (io) "PA4/SPI1_NSS,USART1_CK,TIM14_CH1/ADC_IN4", 11 PA5 (io) "PA5/SPI1_SCK/ADC_IN5", 12 PA6 (io) "PA6/SPI1_MISO,TIM3_CH1,TIM1_BKIN,TIM16_CH1,EVENTOUT/ADC_IN6", 13 PA7 (io) "PA7/SPI1_MOSI,TIM3_CH2,TIM14_CH1,TIM1_CH1N,TIM17_CH1,EVENTOUT/ADC_IN7", 14 PB0 (io) "PB0/TIM3_CH3,TIM1_CH2N,EVENTOUT/ADC_IN8", 15 PB1 (io) "PB1/TIM3_CH4,TIM14_CH1,TIM1_CH3N/ADC_IN9", 18 PA8 (io) "PA8/USART1_CK,TIM1_CH1,EVENTOUT,MCO", 19 PA9 (io) "PA9/USART1_TX,TIM1_CH2,I2C1_SCL", 20 PA10 (io) "PA10/USART1_RX,TIM1_CH3,TIM17_BKIN,I2C1_SDA", 21 PA11 (io) "PA11/USART1_CTS,TIM1_CH4,EVENTOUT", 22 PA12 (io) "PA12/USART1_RTS,TIM1_ETR,EVENTOUT", 23 PA13(SWDIO) (io) "PA13(SWDIO)/IR_OUT,SWDIO", 24 PA14(SWCLK) (io) "PA14(SWCLK)/USART1_TX,SWCLK", 25 PA15 (io) "PA15/SPI1_NSS,USART1_RX,EVENTOUT", 26 PB3 (io) "PB3/SPI1_SCK,EVENTOUT", 27 PB4 (io) "PB4/SPI1_MISO,TIM3_CH1,EVENTOUT", 28 PB5 (io) "PB5/SPI1_MOSI,I2C1_SMBA,TIM16_BKIN,TIM3_CH2", 29 PB6 (io) "PB6/I2C1_SCL,USART1_TX,TIM16_CH1N", 30 PB7 (io) "PB7/I2C1_SDA,USART1_RX,TIM17_CH1N", 31 BOOT0 (in) "Boot memory selection"
part B pins: 1 VDD (power) "Digital power supply", 5 VDDA (power) "Analog power supply", 16 VSS (power) "Ground", 17 VDD (power) "Digital power supply", 32 VSS (power) "Ground"

## STM32F051C6T6
designator U?  (value not drawn)
pins: 1 VBAT, 2 PC13, 3 PC14-OSC32_IN, 4 PC15-OSC32_OUT, 5 PF0-OSC_IN, 6 PF1-OSC_OUT, 7 NRST, 8 VSSA, 9 VDDA, 10 PA0, 11 PA1, 12 PA2, 13 PA3, 14 PA4, 15 PA5, 16 PA6, 17 PA7, 18 PB0, 19 PB1, 20 PB2, 21 PB10, 22 PB11, 23 VSS, 24 VDD, 25 PB12, 26 PB13, 27 PB14, 28 PB15, 29 PA8, 30 PA9, 31 PA10, 32 PA11, 33 PA12, 34 PA13, 35 PF6, 36 PF7, 37 PA14, 38 PA15, 39 PB3, 40 PB4, 41 PB5, 42 PB6, 43 PB7, 44 BOOT0, 45 PB8, 46 PB9, 47 VSS, 48 VDD

## STM32F051C8T6
designator U?
footprint LQFP48
pins: 1 VBAT, 2 PC13, 3 PC14-OSC32_IN, 4 PC15-OSC32_OUT, 5 PF0-OSC_IN, 6 PF1-OSC_OUT, 7 NRST, 8 VSSA, 9 VDDA, 10 PA0, 11 PA1, 12 PA2, 13 PA3, 14 PA4, 15 PA5, 16 PA6, 17 PA7, 18 PB0, 19 PB1, 20 PB2, 21 PB10, 22 PB11, 23 VSS, 24 VDD, 25 PB12, 26 PB13, 27 PB14, 28 PB15, 29 PA8, 30 PA9, 31 PA10, 32 PA11, 33 PA12, 34 PA13, 35 PF6, 36 PF7, 37 PA14, 38 PA15, 39 PB3, 40 PB4, 41 PB5, 42 PB6, 43 PB7, 44 BOOT0, 45 PB8, 46 PB9, 47 VSS, 48 VDD

## T POINT S_0
designator PT?, comment PTO TESTE  (value not drawn)
C_MANF_P/N: DNP; Unit Price1: 0
footprint PT-DX
footprint PT-DX
pins: 1 TP

## TC58BVG0S3HBAI6
designator U?
1Gbit Nand Flash
footprint BGA67
pins: B2 ~{WP}, B3 ALE, B4 VSS, B5 ~{CE}, B6 ~{WE}, B7 R~{B}, C3 ~{RE}, C4 CLE, G3 IO0, G7 VCC, H3 IO1, H5 VCC, H6 IO5, H7 IO7, J2 VSS, J3 IO2, J4 IO3, J5 IO4, J6 IO6, J7 VSS

## TCR3DF10,LM
designator U?
1V LDO
footprint SOT23-5
pins: 1 VIN, 2 GND (power), 3 CE, 4 NC, 5 VOUT (power)

## Test point
designator *  (value not drawn)
footprint Testpoint_35_50
pins: 1

## TLK105L
designator U?
Single Port 10/100 Mb/s Ethernet Physical Layer Transceiver; GROUP: ETH_TLK
footprint QFN32
part A pins: 1 RXD_3/PHYAD4 (hiz) "RECEIVE DATA: Symbols received on the cable are decoded and presented on these pins synchronous to RX_CLK. [see datasheet]", 2 TX_CLK (hiz) "MII TRANSMIT CLOCK: this clock has constant phase referenced to REF_CLK.", 3 TX_EN "TRANSMIT ENABLE: MII_TX_EN is presented on the rising edge of the MII_TX_CLK . [see datasheet]", 4 TXD_0 "TRANSMIT DATA: In MII mode, it is the transmit data nibble received from the MAC that is synchronous to the rising edge of the TX_CLK signal. [see datasheet]", 5 TXD_1 "TRANSMIT DATA: In MII mode, it is the transmit data nibble received from the MAC that is synchronous to the rising edge of the TX_CLK signal. [see datasheet]", 6 TXD_2 "TRANSMIT DATA: In MII mode, it is the transmit data nibble received from the MAC that is synchronous to the rising edge of the TX_CLK signal. [see datasheet]", 7 TXD_3 "TRANSMIT DATA: In MII mode, it is the transmit data nibble received from the MAC that is synchronous to the rising edge of the TX_CLK signal. [see datasheet]", 8 ~{PWR_DWN}/~{INTN} (io) "Register access is required for this pin to be configured either as power down or as an interrupt. The default function of this pin is power down[see datasheet]", 9 RD- (io) "Differential receive input (PMD Input Pair). These differential inputs are automatically configured to accept either 100Base-TX or 10Base-T signaling. [see datasheet]", 10 RD+ (io) "Differential receive input (PMD Input Pair). These differential inputs are automatically configured to accept either 100Base-TX or 10Base-T signaling. [see datasheet]", 11 TD- (io) "Differential common driver transmit output (PMD Output Pair). These differential outputs are automatically configured to either 10Base-T or 100Base-TX signaling. [see datasheet]", 12 TD+ (io) "Differential common driver transmit output (PMD Output Pair). These differential outputs are automatically configured to either 10Base-T or 100Base-TX signaling. [see datasheet]", 16 RBIAS "Bias Resistor Connection. Use a 4.87k ohm 1% resistor connected from RBIAS to GND.", 17 LED_LINK/AN0 (hiz) "LED Pin to indicate status.[see datasheet]", 18 RESETN (in) "This pin is an active-low reset input that initializes or re-initializes all the internal registers of the. [see datasheet]", 19 MDIO (io) "MANAGEMENT DATA I/O: Bidirectional command / data signal synchronized to MDC. Either the local controller or the TLK110 may drive the MDIO signal. [see datasheet]", 20 MDC (in) "MANAGEMENT DATA CLOCK: Clock signal for the management data input/output (MDIO) interface. The maximum MDC rate is 25 MHz; there is no minimum MDC rate. [see datasheet]", 22 XO "CRYSTAL OUTPUT: Reference Clock output. XO pin is used for crystal only. This pin should be left floating when an oscillator input is connected to XI.", 23 XI "MII reference clock Reference clock.  It must be connected to a 50MHz +/-50ppm-tolerance CMOS-level oscillator source.", 25 RX_CLK (hiz) "RECEIVE CLOCK: In MII mode it is the receive clock that provides either a 25MHz or 2.5MHz reference clock, depending on the speed, that is derived from the received data stream", 26 RX_DV/MII_MODE (hiz) "RECEIVE DATA VALID: This pin indicates valid data is present on the RXD [3:0] for MII mode or on RXD [1:0] for RMII mode, independently from Carrier Sense.", 27 CRS/CRS_DV/LED_CFG (hiz) "CARRIER SENSE: In MII mode this pin is asserted high when the receive medium is non-idle. this pin combines the RMII Carrier and Receive Data Valid indications.", 28 RX_ER/AMDIX_EN (hiz) "RECEIVE ERROR: This pin indicates that an error symbol has been detected within a received packet in both MII and RMII mode. [see datasheet]", 29 COL/PHYAD0 (hiz) "COLLISION DETECT: For MII mode in Full Duplex Mode this pin is always low.This pin is not used in RMII mode.[see datasheet]", 30 RXD_0/PHYAD1 (hiz) "RECEIVE DATA: Symbols received on the cable are decoded and presented on these pins synchronous to RX_CLK. [see datasheet]", 31 RXD_1/PHYAD2 (hiz) "RECEIVE DATA: Symbols received on the cable are decoded and presented on these pins synchronous to RX_CLK. [see datasheet]", 32 RXD_2/PHYAD3 (hiz) "RECEIVE DATA: Symbols received on the cable are decoded and presented on these pins synchronous to RX_CLK. [see datasheet]"
part B pins: 13 PFBIN1 (in), 14 AVDD33 (power) "Analog 3.3V power supply", 15 PFBOUT (out), 21 VDD33_IO (power) "I/O 3.3V Supply", 24 PFBIN2 (in), EP GND (power) "Analog ground"

## TPS562209DDCR
designator U?
footprint SOT6 (SOT23, 6-Leads, Body 2,90x2,80mm, Pitch 0,95mm, IPC Medium Density)
pins: 1 GND (power), 2 SW (power), 3 VIN (power), 4 VFB (power), 5 EN (power), 6 VBST (power)

## TRJES101DNL
designator X?  (value not drawn)
RJ45 SMD Horizontal Connector
footprint TRJES101DNL
pins: 1 (power), 2 (power), 3 (power), 4 (power), 5 (power), 6 (power), 7 (power), 8 (power), FR Frame (power)

## USB
designator X?
USB Connector
footprint USBA SMD (USB SMT (1).pdf from Jinglai)
pins: 1 Vbus, 2 D-, 3 D+, 4 GND, S Shield

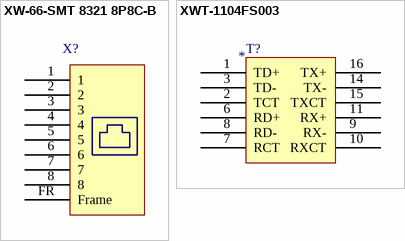
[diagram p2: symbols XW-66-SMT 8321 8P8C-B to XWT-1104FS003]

## XW-66-SMT 8321 8P8C-B
designator X?  (value not drawn)
RJ45 SMD Horizontal Connector
footprint XW-66-SMT 8321 8P8C-B
pins: 1 (power), 2 (power), 3 (power), 4 (power), 5 (power), 6 (power), 7 (power), 8 (power), FR Frame (power)

## XWT-1104FS003
designator T?
XW LAN Transformer
footprint XWT-1104FS003 (XW LAN Transformer)
pins: 1 TD+ (power), 2 TCT (power), 3 TD- (power), 6 RD+ (power), 7 RCT (power), 8 RD- (power), 9 RX- (power), 10 RXCT (power), 11 RX+ (power), 14 TX- (power), 15 TXCT (power), 16 TX+ (power)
